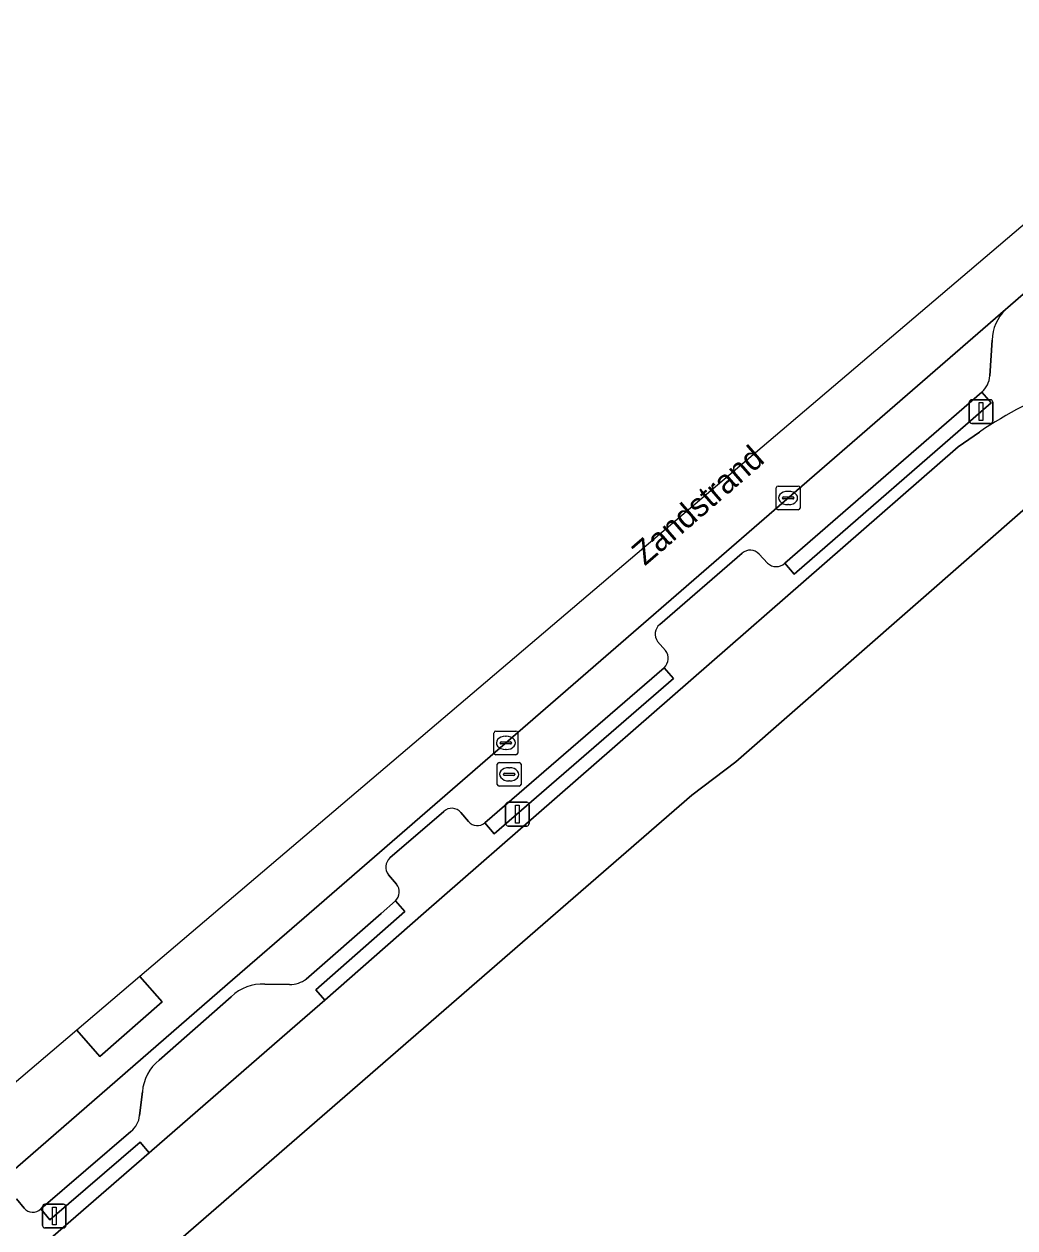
# Model space of a CAD drawing. Extents: x 155640 to 156811, y 382821 to 384049.
# Drawn here: x 156451 to 156492.8, y 383986.7 to 384037.5 of the extents above; entities that cross this region are included whole.
import ezdxf

# ---------------------------------------------------------------- set-up
doc = ezdxf.new("R2010")
doc.units = 0
for name, color, linetype in [('IMGEO_Berm_groen', 7, 'Continuous'), ('IMGEO_Berm_open', 7, 'Continuous'), ('IMGEO_Fietspad_gesloten', 7, 'Continuous'), ('IMGEO_Groenvoorziening', 7, 'Continuous'), ('IMGEO_Kolk', 7, 'Continuous'), ('IMGEO_Lichtmast', 7, 'Continuous'), ('IMGEO_Openbare_ruimte_label', 7, 'Continuous'), ('IMGEO_Parkeervlak_open', 7, 'Continuous'), ('IMGEO_Rijbaan_lokaal_gesloten', 7, 'Continuous'), ('IMGEO_Rijbaan_lokaal_open', 7, 'Continuous'), ('IMGEO_Rioolput', 7, 'Continuous')]:
    doc.layers.add(name, color=color, linetype=linetype)

msp = doc.modelspace()

# ---------------------------------------------------------------- linework, layer by layer
at = {"layer": 'IMGEO_Berm_groen'}
for points in [[(156494.22, 384027.084), (156492.482, 384025.587), (156492.381, 384025.493)], [(156491.821, 384024.208), (156491.728, 384022.69)], [(156491.388, 384022.009), (156491.782, 384021.556), (156483.465, 384014.33), (156483.071, 384014.783)], [(156490.392, 384019.695), (156491.286, 384020.324)], [(156466.647, 384000.534), (156467.043, 384000.083), (156463.282, 383996.784), (156463.665, 383996.347), (156467.831, 384000), (156490.392, 384019.695)], [(156481.281, 384015.213), (156477.797, 384012.199)], [(156482.349, 384014.793), (156481.987, 384015.174)], [(156477.708, 384011.485), (156478.042, 384011.102)], [(156477.987, 384010.378), (156478.38, 384009.924), (156470.812, 384003.37), (156470.419, 384003.824)], [(156468.682, 384004.308), (156466.413, 384002.347)], [(156469.725, 384003.884), (156469.412, 384004.267)], [(156466.349, 384001.636), (156466.697, 384001.245)], [(156456.26, 383989.906), (156455.876, 383990.352), (156452.071, 383987.075), (156451.679, 383987.53)], [(156423.925, 383963.387), (156424.318, 383962.933), (156414.47, 383954.414), (156414.861, 383953.961), (156456.26, 383989.906)], [(156450.979, 383987.562), (156450.66, 383987.952)]]:
    msp.add_lwpolyline(points, dxfattribs=at)
for centre, radius, start, end in [((156493.718, 384024.146), 1.898, 134.7839, 178.1212), ((156490.657, 384022.799), 1.076, 312.7583, 354.179), ((156501.522, 384005.13), 18.32, 110.8969, 123.9661), ((156481.614, 384014.824), 0.512, 43.1486, 130.5277), ((156482.715, 384015.161), 0.519, 225.1666, 313.2464), ((156478.125, 384011.796), 0.52, 129.0945, 216.695), ((156477.607, 384010.771), 0.547, 314.068, 37.2435), ((156469.027, 384003.934), 0.509, 40.8959, 132.6749), ((156470.103, 384004.207), 0.497, 220.5545, 309.563), ((156466.762, 384001.957), 0.523, 131.8688, 217.8441), ((156466.279, 384000.917), 0.531, 313.8294, 38.1254), ((156451.344, 383987.879), 0.484, 220.9836, 313.7816)]:
    msp.add_arc(centre, radius, start, end, dxfattribs=at)
at = {"layer": 'IMGEO_Berm_open'}
for points in [[(156491.782, 384021.556), (156491.388, 384022.009), (156483.071, 384014.783), (156483.465, 384014.33)], [(156478.38, 384009.924), (156477.987, 384010.378), (156470.419, 384003.824), (156470.812, 384003.37)]]:
    msp.add_lwpolyline(points, close=True, dxfattribs=at)
for points in [[(156462.195, 383995.059), (156463.665, 383996.347), (156463.282, 383996.784), (156467.043, 384000.083), (156466.647, 384000.534), (156466.038, 384000), (156462.886, 383997.235)], [(156462.183, 383997.005), (156461.136, 383997.016)], [(156459.717, 383996.489), (156456.681, 383993.818)], [(156455.484, 383990.807), (156451.679, 383987.53), (156452.071, 383987.075), (156455.876, 383990.352), (156456.26, 383989.906), (156462.195, 383995.059)], [(156455.969, 383992.475), (156455.844, 383991.482)]]:
    msp.add_lwpolyline(points, dxfattribs=at)
for centre, radius, start, end in [((156462.177, 383998.213), 1.208, 270.2827, 305.9503), ((156461.024, 383995.144), 1.876, 86.5779, 134.1709), ((156457.878, 383992.323), 1.915, 128.6924, 175.4465), ((156454.965, 383991.517), 0.88, 306.1655, 357.6895)]:
    msp.add_arc(centre, radius, start, end, dxfattribs=at)
at = {"layer": 'IMGEO_Fietspad_gesloten'}
for points in [[(156491.286, 384020.324), (156490.392, 384019.695), (156467.831, 384000), (156463.665, 383996.347), (156462.195, 383995.059), (156456.26, 383989.906), (156414.861, 383953.961), (156410.985, 383950.596), (156412.558, 383947.186), (156464.513, 383992.278)], [(156464.513, 383992.278), (156473.402, 384000), (156479.158, 384005), (156481.006, 384006.405), (156493.456, 384017.313)]]:
    msp.add_lwpolyline(points, dxfattribs=at)
msp.add_arc((156501.522, 384005.13), 18.32, 110.8969, 123.9661, dxfattribs=at)
at = {"layer": 'IMGEO_Groenvoorziening'}
msp.add_lwpolyline([(156493.456, 384017.313), (156481.006, 384006.405), (156479.158, 384005), (156473.402, 384000), (156464.513, 383992.278), (156412.558, 383947.186)], dxfattribs=at)
at = {"layer": 'IMGEO_Kolk'}
for p, q in [((156482.715, 384017.115), (156482.715, 384017.967)), ((156482.79, 384018.041), (156483.642, 384018.041)), ((156483.716, 384017.967), (156483.716, 384017.115)), ((156482.974, 384017.535), (156482.974, 384017.547)), ((156483.412, 384017.498), (156483.014, 384017.498)), ((156483.017, 384017.584), (156483.415, 384017.584)), ((156483.203, 384017.821), (156483.228, 384017.821)), ((156483.458, 384017.547), (156483.458, 384017.535)), ((156483.642, 384017.041), (156482.79, 384017.041)), ((156483.226, 384017.261), (156483.201, 384017.261)), ((156470.805, 384006.776), (156470.805, 384007.628)), ((156470.88, 384007.702), (156471.732, 384007.702)), ((156471.107, 384007.245), (156471.505, 384007.245)), ((156471.293, 384007.482), (156471.318, 384007.482)), ((156471.806, 384007.628), (156471.806, 384006.776)), ((156471.064, 384007.196), (156471.064, 384007.208)), ((156471.502, 384007.159), (156471.104, 384007.159)), ((156471.316, 384006.922), (156471.291, 384006.922)), ((156471.548, 384007.208), (156471.548, 384007.196)), ((156471.732, 384006.702), (156470.88, 384006.702))]:
    msp.add_line(p, q, dxfattribs=at)
for points in [[(156482.715, 384017.115), (156482.715, 384017.967)], [(156482.79, 384018.041), (156483.642, 384018.041)], [(156483.716, 384017.967), (156483.716, 384017.115)], [(156483.642, 384017.041), (156482.79, 384017.041)], [(156470.805, 384006.776), (156470.805, 384007.628)], [(156470.88, 384007.702), (156471.732, 384007.702)], [(156471.806, 384007.628), (156471.806, 384006.776)], [(156471.732, 384006.702), (156470.88, 384006.702)]]:
    msp.add_lwpolyline(points, dxfattribs=at)
for centre, radius, start, end in [((156482.792, 384017.965), 0.0765, 91.552, 178.448), ((156482.792, 384017.965), 0.0765, 91.552, 178.448), ((156483.64, 384017.965), 0.0765, 1.552, 88.448), ((156483.64, 384017.965), 0.0765, 1.552, 88.448), ((156483.014, 384017.544), 0.0403, 85.8775, 175.7526), ((156483.011, 384017.534), 0.0366, 178.938, 274.7102), ((156483.415, 384017.541), 0.043, 264.8664, 352.4533), ((156483.419, 384017.546), 0.0386, 1.7309, 96.639), ((156482.792, 384017.117), 0.0765, 181.552, 268.448), ((156482.792, 384017.117), 0.0765, 181.552, 268.448), ((156483.64, 384017.117), 0.0765, 271.552, 358.448), ((156483.64, 384017.117), 0.0765, 271.552, 358.448), ((156470.882, 384007.626), 0.0765, 91.552, 178.448), ((156470.882, 384007.626), 0.0765, 91.552, 178.448), ((156471.104, 384007.205), 0.0403, 85.8775, 175.7526), ((156471.509, 384007.207), 0.0386, 1.7309, 96.639), ((156471.73, 384007.626), 0.0765, 1.552, 88.448), ((156471.73, 384007.626), 0.0765, 1.552, 88.448), ((156470.882, 384006.778), 0.0765, 181.552, 268.448), ((156470.882, 384006.778), 0.0765, 181.552, 268.448), ((156471.101, 384007.195), 0.0366, 178.938, 274.7102), ((156471.505, 384007.202), 0.043, 264.8664, 352.4533), ((156471.73, 384006.778), 0.0765, 271.552, 358.448), ((156471.73, 384006.778), 0.0765, 271.552, 358.448)]:
    msp.add_arc(centre, radius, start, end, dxfattribs=at)
for centre, major_axis, ratio, start_param, end_param in [((156483.202, 384017.541), (-0.387, 0.002), 0.722429, 4.712389, 7.853982), ((156483.227, 384017.541), (-0.39, 0.002), 0.717154, 1.570796, 4.712389), ((156471.292, 384007.202), (-0.387, 0.002), 0.722429, 4.712389, 7.853982), ((156471.317, 384007.202), (-0.39, 0.002), 0.717154, 1.570796, 4.712389)]:
    msp.add_ellipse(centre, major_axis=major_axis, ratio=ratio, start_param=start_param, end_param=end_param, dxfattribs=at)
at = {"layer": 'IMGEO_Lichtmast'}
for p, q in [((156490.86, 384020.789), (156490.86, 384021.589)), ((156490.86, 384021.589), (156490.86, 384020.789)), ((156490.96, 384021.689), (156491.75, 384021.689)), ((156491.75, 384021.689), (156490.96, 384021.689)), ((156491.85, 384021.589), (156491.85, 384020.789)), ((156491.85, 384020.789), (156491.85, 384021.589)), ((156491.75, 384020.689), (156490.96, 384020.689)), ((156490.96, 384020.689), (156491.75, 384020.689)), ((156471.397, 384004.695), (156472.187, 384004.695)), ((156472.187, 384004.695), (156471.397, 384004.695)), ((156471.297, 384003.795), (156471.297, 384004.595)), ((156471.297, 384004.595), (156471.297, 384003.795)), ((156472.287, 384004.595), (156472.287, 384003.795)), ((156472.287, 384003.795), (156472.287, 384004.595)), ((156472.187, 384003.695), (156471.397, 384003.695)), ((156471.397, 384003.695), (156472.187, 384003.695)), ((156451.757, 383986.83), (156451.757, 383987.63)), ((156451.757, 383987.63), (156451.757, 383986.83)), ((156451.857, 383987.73), (156452.647, 383987.73)), ((156452.647, 383987.73), (156451.857, 383987.73)), ((156452.747, 383987.63), (156452.747, 383986.83)), ((156452.747, 383986.83), (156452.747, 383987.63)), ((156452.647, 383986.73), (156451.857, 383986.73)), ((156451.857, 383986.73), (156452.647, 383986.73))]:
    msp.add_line(p, q, dxfattribs=at)
for points in [[(156491.28, 384021.564), (156491.43, 384021.564), (156491.43, 384020.814), (156491.28, 384020.814), (156491.28, 384021.564)], [(156471.717, 384004.57), (156471.867, 384004.57), (156471.867, 384003.82), (156471.717, 384003.82), (156471.717, 384004.57)], [(156452.177, 383987.605), (156452.327, 383987.605), (156452.327, 383986.855), (156452.177, 383986.855), (156452.177, 383987.605)]]:
    msp.add_lwpolyline(points, dxfattribs=at)
for centre, start, end in [((156490.96, 384021.589), 90, 180), ((156490.96, 384021.589), 90, 180), ((156491.75, 384021.589), 0, 90), ((156491.75, 384021.589), 360, 90), ((156490.96, 384020.789), 180, 270), ((156490.96, 384020.789), 180, 270), ((156491.75, 384020.789), 270, 0), ((156491.75, 384020.789), 270, 0), ((156471.397, 384004.595), 90, 180), ((156471.397, 384004.595), 90, 180), ((156472.187, 384004.595), 0, 90), ((156472.187, 384004.595), 360, 90), ((156471.397, 384003.795), 180, 270), ((156471.397, 384003.795), 180, 270), ((156472.187, 384003.795), 270, 0), ((156472.187, 384003.795), 270, 0), ((156451.857, 383987.63), 90, 180), ((156451.857, 383987.63), 90, 180), ((156452.647, 383987.63), 0, 90), ((156452.647, 383987.63), 360, 90), ((156451.857, 383986.83), 180, 270), ((156451.857, 383986.83), 180, 270), ((156452.647, 383986.83), 270, 0), ((156452.647, 383986.83), 270, 0)]:
    msp.add_arc(centre, 0.1, start, end, dxfattribs=at)
at = {"layer": 'IMGEO_Parkeervlak_open'}
for points in [[(156492.381, 384025.493), (156463.008, 384000), (156459.568, 383997.014), (156410.443, 383954.286)], [(156491.728, 384022.69), (156491.821, 384024.208)], [(156483.071, 384014.783), (156491.388, 384022.009)], [(156477.797, 384012.199), (156481.281, 384015.213)], [(156481.987, 384015.174), (156482.349, 384014.793)], [(156478.042, 384011.102), (156477.708, 384011.485)], [(156470.419, 384003.824), (156477.987, 384010.378)], [(156466.413, 384002.347), (156468.682, 384004.308)], [(156469.412, 384004.267), (156469.725, 384003.884)], [(156466.697, 384001.245), (156466.349, 384001.636)], [(156462.886, 383997.235), (156466.038, 384000), (156466.647, 384000.534)], [(156461.136, 383997.016), (156462.183, 383997.005)], [(156456.681, 383993.818), (156459.717, 383996.489)], [(156455.844, 383991.482), (156455.969, 383992.475)], [(156451.679, 383987.53), (156455.484, 383990.807)], [(156450.66, 383987.952), (156450.979, 383987.562)]]:
    msp.add_lwpolyline(points, dxfattribs=at)
for centre, radius, start, end in [((156493.718, 384024.146), 1.898, 134.7839, 178.1212), ((156490.657, 384022.799), 1.076, 312.7583, 354.179), ((156481.614, 384014.824), 0.512, 43.1486, 130.5277), ((156482.715, 384015.161), 0.519, 225.1666, 313.2464), ((156478.125, 384011.796), 0.52, 129.0945, 216.695), ((156477.607, 384010.771), 0.547, 314.068, 37.2435), ((156469.027, 384003.934), 0.509, 40.8959, 132.6749), ((156470.103, 384004.207), 0.497, 220.5545, 309.563), ((156466.762, 384001.957), 0.523, 131.8688, 217.8441), ((156466.279, 384000.917), 0.531, 313.8294, 38.1254), ((156462.177, 383998.213), 1.208, 270.2827, 305.9503), ((156461.024, 383995.144), 1.876, 86.5779, 134.1709), ((156457.878, 383992.323), 1.915, 128.6924, 175.4465), ((156454.965, 383991.517), 0.88, 306.1655, 357.6895), ((156451.344, 383987.879), 0.484, 220.9836, 313.7816)]:
    msp.add_arc(centre, radius, start, end, dxfattribs=at)
at = {"layer": 'IMGEO_Rijbaan_lokaal_gesloten'}
for points in [[(156503.1, 384037.543), (156455.868, 383997.337), (156456.798, 383996.277), (156454.172, 383993.966), (156453.209, 383995.074), (156408.038, 383956.623)], [(156408.038, 383956.623), (156410.443, 383954.286), (156459.568, 383997.014), (156463.008, 384000), (156492.381, 384025.493), (156492.482, 384025.587), (156494.22, 384027.084)]]:
    msp.add_lwpolyline(points, dxfattribs=at)
at = {"layer": 'IMGEO_Rijbaan_lokaal_open'}
msp.add_lwpolyline([(156453.209, 383995.074), (156454.172, 383993.966), (156456.798, 383996.277), (156455.868, 383997.337)], close=True, dxfattribs=at)
at = {"layer": 'IMGEO_Rioolput'}
for p, q in [((156470.944, 384005.45), (156470.944, 384006.302)), ((156471.019, 384006.376), (156471.871, 384006.376)), ((156471.945, 384006.302), (156471.945, 384005.45)), ((156471.203, 384005.87), (156471.203, 384005.882)), ((156471.641, 384005.833), (156471.243, 384005.833)), ((156471.246, 384005.919), (156471.644, 384005.919)), ((156471.432, 384006.156), (156471.457, 384006.156)), ((156471.687, 384005.882), (156471.687, 384005.87)), ((156471.871, 384005.376), (156471.019, 384005.376)), ((156471.455, 384005.596), (156471.43, 384005.596))]:
    msp.add_line(p, q, dxfattribs=at)
for points in [[(156470.944, 384005.45), (156470.944, 384006.302)], [(156471.019, 384006.376), (156471.871, 384006.376)], [(156471.945, 384006.302), (156471.945, 384005.45)], [(156471.871, 384005.376), (156471.019, 384005.376)]]:
    msp.add_lwpolyline(points, dxfattribs=at)
for centre, radius, start, end in [((156471.021, 384006.3), 0.0765, 91.552, 178.448), ((156471.021, 384006.3), 0.0765, 91.552, 178.448), ((156471.869, 384006.3), 0.0765, 1.552, 88.448), ((156471.869, 384006.3), 0.0765, 1.552, 88.448), ((156471.243, 384005.879), 0.0403, 85.8775, 175.7526), ((156471.24, 384005.869), 0.0366, 178.938, 274.7102), ((156471.644, 384005.876), 0.043, 264.8664, 352.4533), ((156471.648, 384005.881), 0.0386, 1.7309, 96.639), ((156471.021, 384005.452), 0.0765, 181.552, 268.448), ((156471.021, 384005.452), 0.0765, 181.552, 268.448), ((156471.869, 384005.452), 0.0765, 271.552, 358.448), ((156471.869, 384005.452), 0.0765, 271.552, 358.448)]:
    msp.add_arc(centre, radius, start, end, dxfattribs=at)
for centre, major_axis, ratio, start_param, end_param in [((156471.431, 384005.876), (-0.387, 0.002), 0.722429, 4.712389, 7.853982), ((156471.456, 384005.876), (-0.39, 0.002), 0.717154, 1.570796, 4.712389)]:
    msp.add_ellipse(centre, major_axis=major_axis, ratio=ratio, start_param=start_param, end_param=end_param, dxfattribs=at)

# ---------------------------------------------------------------- texts
at = {"layer": 'IMGEO_Openbare_ruimte_label'}
msp.add_text('Zandstrand', height=1, rotation=40.9057, dxfattribs=at).set_placement((156477.17, 384014.65))

doc.saveas('drawing.dxf')
